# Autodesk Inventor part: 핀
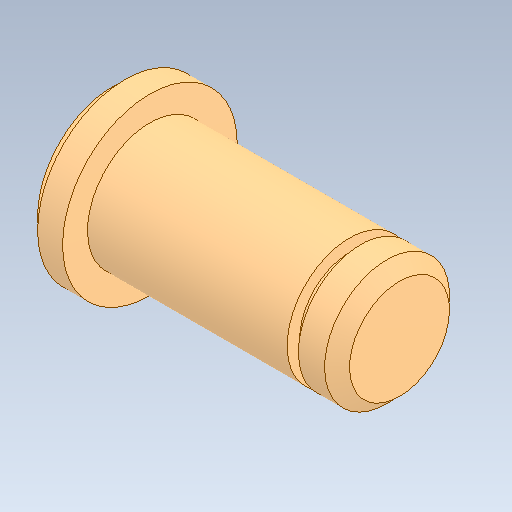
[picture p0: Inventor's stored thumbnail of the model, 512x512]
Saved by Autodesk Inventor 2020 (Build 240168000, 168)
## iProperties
Created: 2024-08
Part Number: 핀
Material: 강철, 탄소
Document SubType Name: Modeling
Designer: oem
Density: 7.85 g/cm^3
Appearance: 기본값
Author: jhkim
Sending System: Autodesk Inventor 2025
Preprocessor: ST-DEVELOPER v20
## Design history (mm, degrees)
node "핀1"
node "솔리드2"
node "솔리드1"
